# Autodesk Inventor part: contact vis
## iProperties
Created: 2002-04
Part Number: contact vis
Material: Par défaut
Document SubType Name: Modélisation
Designer: BAVERGE
Control State: 0
Master: False
Checked Out: False
Shininess: 20.0
Length Units: 11269
Angle Units: 11279
Time Units: 11290
Mass Units: 11283
Length Display Precision: 3
Angle Display Precision: 2
Density: 0.0
Volumn: 0.0
Area: 0.0
PropertySet Name: Model Information
Author: BAVERGE
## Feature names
1. Révolution1 [Revolution]
2. Chanfrein1 [Chamfer]
3. Extrusion1
